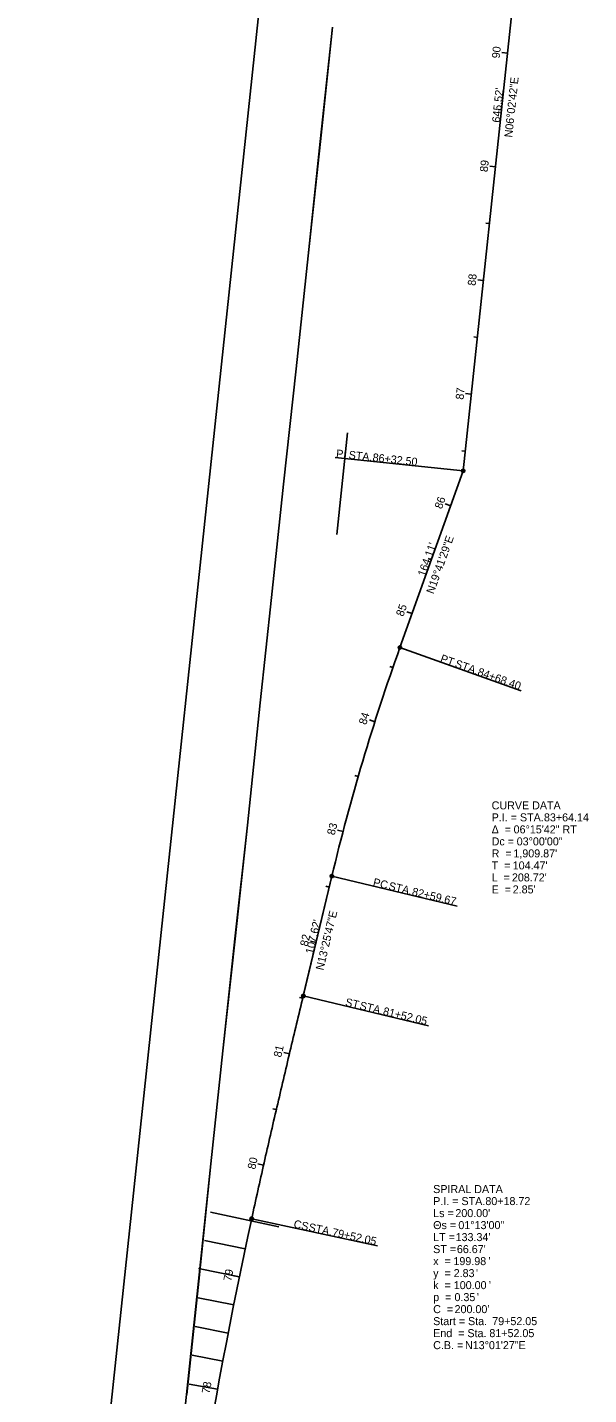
# Model space of a CAD drawing. Extents: x 172104 to 172774, y 250510 to 260293.
# Drawn here: x 172173 to 172663, y 254719 to 255915 of the extents above; entities that cross this region are included whole.
import ezdxf

# ---------------------------------------------------------------- set-up
doc = ezdxf.new("R2010")
doc.units = 0
for name, color, linetype in [('DT_P_Break_Line', 7, 'Continuous'), ('DT_P_Contour_Major', 7, 'Continuous'), ('DT_P_Contour_Minor', 7, 'Continuous'), ('DT_P_Spot_Elevations', 7, 'Continuous'), ('DT_P_Terrain_Boundary', 7, 'Continuous'), ('DT_P_Triangles', 7, 'Continuous'), ('DT_P_Void', 7, 'Continuous'), ('DT_X_Spot_Elev', 7, 'Continuous'), ('MD_P_Surface_Ditch', 7, 'Continuous')]:
    doc.layers.add(name, color=color, linetype=linetype)

msp = doc.modelspace()

# ---------------------------------------------------------------- linework, layer by layer
at = {"layer": 'DT_P_Contour_Minor'}
for p, q in [((172553.7, 255526.8), (172621.7, 256168.7)), ((172498.4, 255372.3), (172553.7, 255526.8)), ((172414, 255067.6), (172438.9, 255172.3))]:
    msp.add_line(p, q, dxfattribs=at)
for centre, radius, start, end in [((174296.6, 254728.7), 1909.9, 160.3087, 166.5704), ((176971.6, 253876.6), 4709.3, 167.7871, 173.9419)]:
    msp.add_arc(centre, radius, start, end, dxfattribs=at)
msp.add_open_spline([(172368.9, 254872.8), (172372.4, 254889.1), (172379.6, 254921.6), (172390.9, 254970.3), (172402.3, 255019), (172410.1, 255051.4), (172414, 255067.6)], degree=3, dxfattribs=at)
at = {"layer": 'DT_P_Spot_Elevations'}
for p, q in [((172553.7, 255526.8), (172441.8, 255538.6)), ((172498.4, 255372.3), (172604.3, 255334.4)), ((172438.9, 255172.3), (172548.4, 255146.2)), ((172414, 255067.6), (172523.4, 255041.5)), ((172368.9, 254872.8), (172478.8, 254849))]:
    msp.add_line(p, q, dxfattribs=at)
for centre in [(172553.7, 255526.8), (172498.4, 255372.3), (172438.9, 255172.3), (172414, 255067.6), (172368.9, 254872.8)]:
    msp.add_circle(centre, 1.5, dxfattribs=at)
at = {"layer": 'DT_P_Terrain_Boundary'}
msp.add_line((172172.9, 254022), (172391.8, 256084.9), dxfattribs=at)
msp.add_line((172172.9, 254022), (172391.8, 256084.9), dxfattribs=at)
at = {"layer": 'DT_P_Triangles'}
for p, q in [((172428.8, 255814.8), (172439.5, 255914.8)), ((172428.9, 255814.8), (172439.5, 255914.8)), ((172418.2, 255714.9), (172428.8, 255814.8)), ((172418.2, 255714.9), (172428.9, 255814.8)), ((172407.7, 255616.2), (172418.2, 255714.9)), ((172407.7, 255616.2), (172418.2, 255714.9)), ((172396.8, 255515.3), (172407.7, 255616.2)), ((172396.8, 255515.3), (172407.7, 255616.2)), ((172443.3, 255471.1), (172452.7, 255560.1)), ((172498.4, 255372.3), (172553.7, 255526.8)), ((172386.2, 255416.1), (172396.8, 255515.3)), ((172386.2, 255416.1), (172396.8, 255515.3)), ((172376.2, 255323.9), (172386.2, 255416.1)), ((172376.3, 255323.9), (172386.2, 255416.1)), ((172365.1, 255216.9), (172376.2, 255323.9)), ((172365.1, 255216.9), (172376.3, 255323.9)), ((172354.3, 255117.6), (172365.1, 255216.9)), ((172354.4, 255117.5), (172365.1, 255216.9)), ((172407.2, 255039.2), (172438.9, 255172.3)), ((172343.8, 255019.5), (172354.3, 255117.6)), ((172343.8, 255019.5), (172354.4, 255117.5)), ((172333.1, 254920.8), (172343.8, 255019.5)), ((172333.2, 254920.8), (172343.8, 255019.5)), ((172322.5, 254818.3), (172333.1, 254920.8)), ((172322.6, 254818.3), (172333.2, 254920.8)), ((172312, 254718.9), (172322.5, 254818.3)), ((172312.1, 254718.9), (172322.6, 254818.3)), ((172301.3, 254618.7), (172312, 254718.9))]:
    msp.add_line(p, q, dxfattribs=at)
for centre, radius, start, end in [((174296.6, 254728.7), 1909.9, 160.3087, 166.5704), ((176971.6, 253876.6), 4709.3, 167.7871, 173.9419)]:
    msp.add_arc(centre, radius, start, end, dxfattribs=at)
msp.add_open_spline([(172368.9, 254872.8), (172372.4, 254889.1), (172379.6, 254921.6), (172390.9, 254970.3), (172402.3, 255019), (172410.1, 255051.4), (172414, 255067.6)], degree=3, dxfattribs=at)
at = {"layer": 'DT_P_Void'}
for p, q in [((172592.4, 255892.2), (172587.4, 255892.8)), ((172587.1, 255842.5), (172584.2, 255842.8)), ((172581.9, 255792.8), (172576.9, 255793.3)), ((172576.6, 255743.1), (172573.6, 255743.4)), ((172571.3, 255693.4), (172566.4, 255693.9)), ((172566.1, 255643.6), (172563.1, 255644)), ((172560.8, 255593.9), (172555.8, 255594.4)), ((172555.5, 255544.2), (172552.6, 255544.5)), ((172542.8, 255496.2), (172538, 255497.9)), ((172525.9, 255449.1), (172523.1, 255450.1)), ((172509.1, 255402), (172504.4, 255403.7)), ((172492.3, 255354.9), (172489.5, 255355.9)), ((172476.5, 255307.5), (172471.8, 255309)), ((172462, 255259.6), (172459.1, 255260.5)), ((172448.7, 255211.4), (172443.9, 255212.7)), ((172436.7, 255162.9), (172433.8, 255163.6)), ((172425.1, 255114.3), (172420.2, 255115.4)), ((172413.5, 255065.6), (172410.6, 255066.3)), ((172401.9, 255017), (172397, 255018.2)), ((172390.4, 254968.3), (172387.5, 254969)), ((172379.2, 254919.6), (172374.4, 254920.7)), ((172368.4, 254870.8), (172365.5, 254871.4)), ((172358.2, 254821.9), (172353.3, 254822.9)), ((172348.4, 254772.8), (172345.4, 254773.4)), ((172339.1, 254723.7), (172334.2, 254724.6))]:
    msp.add_line(p, q, dxfattribs=at)
at = {"layer": 'MD_P_Surface_Ditch'}
for p, q in [((172332.8, 254878.5), (172392.5, 254865.6)), ((172327.6, 254853.8), (172363.2, 254846.3)), ((172322.5, 254829.2), (172358.2, 254821.9)), ((172322.2, 254803.5), (172353.2, 254797.4)), ((172319.5, 254778.4), (172348.4, 254772.8)), ((172316.8, 254753.3), (172343.7, 254748.3)), ((172314.2, 254728.2), (172339.1, 254723.7))]:
    msp.add_line(p, q, dxfattribs=at)

# ---------------------------------------------------------------- texts
at = {"layer": 'DT_P_Break_Line'}
for s, rotation, p in [("645.52'", 83.955, (172585.8, 255831.2)), ("164.11'", 70.3087, (172520.3, 255433.9)), ("107.62'", 76.5704, (172422.5, 255103.8))]:
    msp.add_text(s, height=7, rotation=rotation, dxfattribs=at).set_placement(p)
at = {"layer": 'DT_P_Contour_Major'}
for s, rotation, p in [('N06°02\'42"E', 83.955, (172596.6, 255818.2)), ('N19°41\'29"E', 70.3087, (172527.8, 255418.7)), ('N13°25\'47"E', 76.5704, (172431.5, 255089.6))]:
    msp.add_text(s, height=7, rotation=rotation, dxfattribs=at).set_placement(p)
at = {"layer": 'DT_P_Spot_Elevations'}
for s, rotation, p in [('PI', 353.955, (172442.4, 255538.7)), (' STA. ', 353.955, (172450.8, 255537.8)), ('86+32.50', 353.955, (172474.3, 255535.3)), ('PT', 340.3087, (172533.1, 255360)), (' STA. ', 340.3087, (172543.5, 255356.3)), ('84+68.40', 340.3087, (172565.7, 255348.3)), ('PC', 346.5704, (172474.4, 255164)), (' STA. ', 346.5704, (172485.5, 255161.3)), ('82+59.67', 346.5704, (172508.5, 255155.8)), ('ST', 346.5704, (172450.2, 255059.1)), (' STA. ', 346.5704, (172460.2, 255056.7)), ('81+52.05', 346.5704, (172483.2, 255051.2)), ('CS', 347.7871, (172405.1, 254865.1)), (' STA. ', 347.7871, (172415.6, 254862.8)), ('79+52.05', 347.7871, (172438.7, 254857.8))]:
    msp.add_text(s, height=7, rotation=rotation, dxfattribs=at).set_placement(p)
at = {"layer": 'DT_P_Void'}
for s, rotation, p in [('90', 83.955, (172585.6, 255887.4)), ('89', 83.955, (172575.1, 255788)), ('88', 83.955, (172564.5, 255688.5)), ('87', 83.955, (172554, 255588.9)), ('86', 70.3087, (172535, 255493)), ('85', 70.3087, (172501.3, 255399)), ('84', 72.3606, (172468.9, 255304.3)), ('83', 75.3606, (172441.3, 255207.8)), ('82', 76.5704, (172417.8, 255110.5)), ('81', 76.6528, (172394.6, 255013.5)), ('80', 77.2736, (172371.9, 254915.5)), ('79', 78.4204, (172350.9, 254817.7)), ('78', 79.637, (172332, 254719.4))]:
    msp.add_text(s, height=7, rotation=rotation, dxfattribs=at).set_placement(p)
at = {"layer": 'DT_X_Spot_Elev'}
for s, p in [('CURVE DATA', (172578.6, 255230.8)), ('P.I. = STA. ', (172578.6, 255220.3)), ('83+64.14', (172624.3, 255220.3)), ('Δ  = ', (172578.6, 255209.8)), ('06°15\'42" RT', (172597.8, 255209.8)), ('Dc = ', (172578.6, 255199.3)), ('03°00\'00"', (172600.5, 255199.3)), ('R  = ', (172578.6, 255188.8)), ("1,909.87'", (172597.6, 255188.8)), ('T  = ', (172578.6, 255178.3)), ('L  = ', (172578.6, 255167.8)), ("208.72'", (172596.3, 255167.8)), ("104.47'", (172597, 255178.3)), ('E  = ', (172578.6, 255157.3)), ("2.85'", (172597, 255157.3))]:
    msp.add_text(s, height=7, dxfattribs=at).set_placement(p)
for s, p in [('SPIRAL DATA', (172527.5, 254895.2)), ('P.I. = STA. ', (172527.5, 254884.7)), ('80+18.72', (172573.1, 254884.7)), ('Ls = ', (172527.5, 254874.2)), ("200.00'", (172546.9, 254874.2)), ('Θs = ', (172527.5, 254863.7)), ('01°13\'00"', (172549.5, 254863.7)), ('LT = ', (172527.5, 254853.2)), ("133.34'", (172547.1, 254853.2)), ('ST = ', (172527.5, 254842.7)), ("66.67'", (172548.2, 254842.7)), ('x  = ', (172527.5, 254832.2)), ('2.83', (172545.4, 254821.7)), ('199.98', (172545.2, 254832.2)), ("'", (172564.9, 254821.7)), ("'", (172575.9, 254832.2)), ('y  = ', (172527.5, 254821.7)), ('k  = ', (172527.5, 254811.2)), ('100.00', (172545.5, 254811.2)), ("'", (172576.2, 254811.2)), ('p  = ', (172527.5, 254800.7)), ('0.35', (172546.1, 254800.7)), ("'", (172565.7, 254800.7)), ('C  = ', (172527.5, 254790.2)), ("200.00'", (172546.2, 254790.2)), ('Start = Sta. ', (172527.5, 254779.7)), ('79+52.05', (172579.1, 254779.7)), ('End  = Sta. ', (172527.5, 254769.2)), ('81+52.05', (172576.6, 254769.2)), ('C.B. = ', (172527.5, 254758.7)), ('N13°01\'27"E', (172555.3, 254758.7))]:
    msp.add_text(s, height=7, rotation=360, dxfattribs=at).set_placement(p)

doc.saveas('drawing.dxf')
